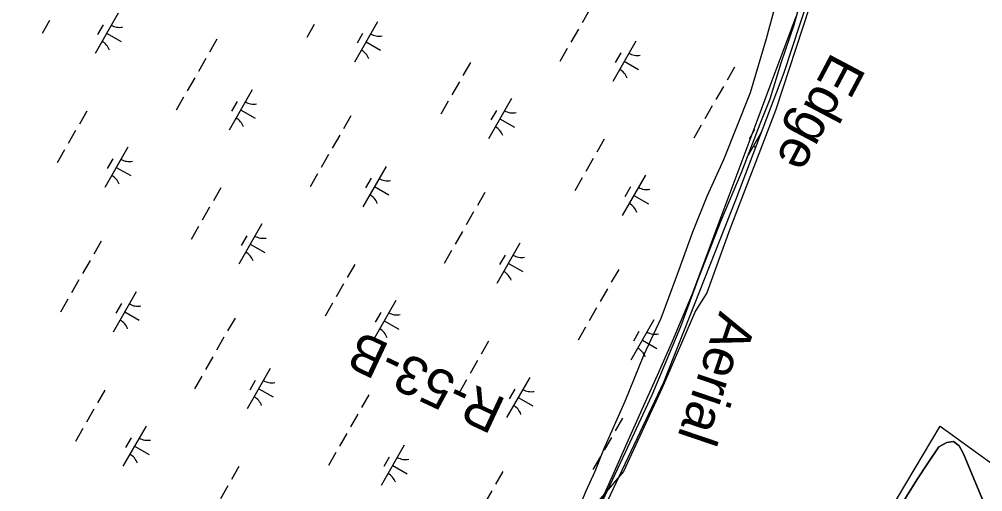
# Model space of a CAD drawing. Extents: x 3930721 to 3950824, y 220441 to 242861.
# Drawn here: x 3939555 to 3940593, y 231818 to 232327 of the extents above; entities that cross this region are included whole.
import ezdxf

# ---------------------------------------------------------------- set-up
doc = ezdxf.new("R2010")
doc.units = 0
for name, color, linetype in [('V-RIVR-EDGE', 7, 'Continuous'), ('V-RIVR-IDEN', 7, 'Continuous'), ('V-RIVR-JETY', 7, 'Continuous'), ('V-RIVR-RANG-IDEN', 7, 'Continuous'), ('V-RRAP-FSHR', 7, 'Continuous'), ('V-TOPO-DPTH', 7, 'Continuous'), ('V-TOPO-MINR', 7, 'Continuous'), ('V-WETL-SWMP', 7, 'Continuous')]:
    doc.layers.add(name, color=color, linetype=linetype)

msp = doc.modelspace()

# ---------------------------------------------------------------- linework, layer by layer
at = {"layer": 'V-RIVR-EDGE'}
msp.add_lwpolyline([(3940577.2, 232885.8), (3940558.8, 232826.5), (3940539.3, 232702.6), (3940479.9, 232552.1), (3940456.4, 232500.9), (3940475.8, 232475.3), (3940468.7, 232441.6), (3940446.1, 232416), (3940426.7, 232394.5), (3940406.2, 232340.2), (3940369.4, 232228.6), (3940320.2, 232100.7), (3940295.7, 232032.1), (3940283.4, 232012.6), (3940247.5, 231929.7), (3940205.6, 231839.6), (3940176.9, 231805.8)], dxfattribs=at)
at = {"layer": 'V-RIVR-JETY'}
for points in [[(3940313.8, 232175.7), (3940342.7, 232248), (3940360, 232306), (3940376.3, 232367.7), (3940382.7, 232392.9), (3940390.4, 232413.5), (3940400.7, 232439.7), (3940410.2, 232460.6)], [(3940461.3, 232442.4), (3940441.4, 232433.4), (3940428.1, 232424.8), (3940420, 232416.9), (3940415.9, 232407.4), (3940406.7, 232384), (3940389.2, 232320.6), (3940375.4, 232279.6), (3940363.4, 232240.7), (3940352.8, 232213.9), (3940332.7, 232161.4), (3940310.5, 232109.7), (3940286.6, 232048.3), (3940267.2, 231995.4), (3940236.4, 231921.8), (3940207.4, 231859.8), (3940177.5, 231795.6)], [(3940156.3, 231796.3), (3940165.7, 231818.8), (3940175.2, 231839.8), (3940185, 231864.4), (3940207.4, 231915.2), (3940227.8, 231965), (3940246.5, 232004.6), (3940263, 232049.2), (3940280.4, 232097.9), (3940296, 232136.2), (3940313.8, 232175.7)]]:
    msp.add_lwpolyline(points, dxfattribs=at)
at = {"layer": 'V-RRAP-FSHR'}
msp.add_lwpolyline([(3940391.6, 232329.6), (3940377.6, 232292.1), (3940363.5, 232254.7), (3940349.5, 232217.2), (3940335.4, 232179.7), (3940321.4, 232142.3), (3940307.3, 232104.8), (3940293.3, 232067.4), (3940279.3, 232029.9), (3940258.2, 231979.5), (3940241.9, 231943), (3940225.6, 231906.4), (3940209.3, 231869.9), (3940193.1, 231833.4), (3940176.7, 231796.9)], dxfattribs=at)
at = {"layer": 'V-TOPO-DPTH'}
msp.add_lwpolyline([(3939138.4, 228899.8), (3939165.6, 228949.6), (3939838.2, 229801.2), (3940275.6, 230709.6), (3940672.4, 231617.7), (3940572, 231858.6), (3940567.3, 231867.1), (3940561.5, 231871.8), (3940554.1, 231870.8), (3940545.6, 231866.1), (3940533.6, 231848.4), (3940521.9, 231830.6), (3940510.6, 231812.5), (3940499.5, 231794.3), (3940486, 231771.5), (3940470.4, 231745.8), (3940454.4, 231720.3), (3940437.9, 231695.2), (3940421, 231670.3), (3940394.3, 231631.9), (3940546.9, 231888.2), (3940838.9, 231677.1)], dxfattribs=at)
at = {"layer": 'V-TOPO-MINR'}
msp.add_lwpolyline([(3940394.3, 231631.9), (3940421, 231670.3), (3940437.9, 231695.2), (3940454.4, 231720.3), (3940470.4, 231745.8), (3940486, 231771.5), (3940499.5, 231794.3), (3940510.6, 231812.5), (3940521.9, 231830.6), (3940533.6, 231848.4), (3940545.6, 231866.1), (3940554.1, 231870.8), (3940561.5, 231871.8), (3940567.3, 231867.1), (3940572, 231858.6), (3940672.4, 231617.7), (3940275.6, 230709.6), (3939838.2, 229801.2), (3939165.6, 228949.6), (3939138.4, 228899.8)], dxfattribs=at)
at = {"layer": 'V-WETL-SWMP'}
for p, q in [((3940379, 232269.5), (3940404.7, 232348.5)), ((3939661.2, 232333.5), (3939636.3, 232290.1)), ((3940169, 232336.9), (3940161.1, 232323.1)), ((3939587.4, 232325.5), (3939579.5, 232311.6)), ((3939645, 232320.8), (3939639.1, 232310.4)), ((3939872.6, 232321.2), (3939864.6, 232307.3)), ((3939940.7, 232324), (3939915.9, 232280.7)), ((3939648.7, 232311.8), (3939664.4, 232302.9)), ((3939924.6, 232311.4), (3939918.6, 232301)), ((3940157.1, 232316.1), (3940149.1, 232302.2)), ((3939767.5, 232305.3), (3939759.6, 232291.4)), ((3939928.3, 232302.4), (3939943.9, 232293.4)), ((3940218.9, 232303.3), (3940194.1, 232259.9)), ((3940145.2, 232295.3), (3940137.2, 232281.4)), ((3940202.8, 232290.6), (3940196.8, 232280.2)), ((3939755.6, 232284.5), (3939747.7, 232270.6)), ((3940040.8, 232280.2), (3940032.8, 232266.3)), ((3940206.5, 232281.6), (3940222.1, 232272.6)), ((3940325.3, 232275.1), (3940317.3, 232261.2)), ((3940326.7, 232132.4), (3940379, 232269.5)), ((3939743.7, 232263.7), (3939735.7, 232249.8)), ((3940028.9, 232259.4), (3940020.9, 232245.5)), ((3939805.5, 232250.8), (3939780.7, 232207.4)), ((3940313.4, 232254.3), (3940305.4, 232240.4)), ((3939731.8, 232242.9), (3939723.8, 232229)), ((3939789.4, 232238.2), (3939783.4, 232227.8)), ((3940016.9, 232238.6), (3940009, 232224.7)), ((3940085, 232241.4), (3940060.2, 232198)), ((3939627.4, 232227.8), (3939619.4, 232213.9)), ((3939793.1, 232229.1), (3939808.7, 232220.2)), ((3940068.9, 232228.7), (3940062.9, 232218.3)), ((3940301.4, 232233.5), (3940293.5, 232219.6)), ((3939911.9, 232222.7), (3939903.9, 232208.8)), ((3940072.6, 232219.7), (3940088.2, 232210.7)), ((3939615.4, 232207), (3939607.5, 232193.1)), ((3940289.5, 232212.6), (3940281.5, 232198.7)), ((3940354.5, 232205.4), (3940338.4, 232177.2)), ((3940347.1, 232208), (3940341.2, 232197.5)), ((3939900, 232201.8), (3939892, 232188)), ((3940185.1, 232197.6), (3940177.2, 232183.7)), ((3940350.8, 232198.9), (3940351.8, 232198.3)), ((3939603.5, 232186.1), (3939595.6, 232172.2)), ((3939671.6, 232188.9), (3939646.8, 232145.6)), ((3939655.5, 232176.3), (3939649.5, 232165.9)), ((3939888, 232181), (3939880.1, 232167.1)), ((3940173.2, 232176.7), (3940165.2, 232162.8)), ((3939659.2, 232167.2), (3939674.8, 232158.3)), ((3939949.9, 232168.2), (3939925, 232124.8)), ((3939876.1, 232160.2), (3939868.1, 232146.3)), ((3939933.7, 232155.5), (3939927.8, 232145.1)), ((3940161.3, 232155.9), (3940153.3, 232142)), ((3940229.4, 232158.7), (3940204.5, 232115.3)), ((3939771.7, 232145.1), (3939763.8, 232131.2)), ((3939937.4, 232146.5), (3939953, 232137.5)), ((3940213.2, 232146.1), (3940207.3, 232135.6)), ((3940056.2, 232140), (3940048.3, 232126.1)), ((3940217, 232137), (3940232.6, 232128.1)), ((3940249.1, 231935.8), (3940326.7, 232132.4)), ((3939759.8, 232124.3), (3939751.8, 232110.4)), ((3940044.3, 232119.2), (3940036.3, 232105.3)), ((3939747.9, 232103.5), (3939739.9, 232089.6)), ((3939816, 232106.3), (3939791.1, 232062.9)), ((3939799.8, 232093.6), (3939793.9, 232083.2)), ((3940032.4, 232098.3), (3940024.4, 232084.5)), ((3939642.8, 232087.6), (3939634.9, 232073.7)), ((3939803.6, 232084.6), (3939819.2, 232075.6)), ((3940094.2, 232085.5), (3940069.3, 232042.1)), ((3940020.4, 232077.5), (3940012.5, 232063.6)), ((3940078.1, 232072.8), (3940072.1, 232062.4)), ((3939630.9, 232066.7), (3939622.9, 232052.9)), ((3939916.1, 232062.5), (3939908.1, 232048.6)), ((3940081.8, 232063.8), (3940097.4, 232054.9)), ((3940298.2, 232060.3), (3940297.7, 232059.3)), ((3940200.6, 232057.3), (3940192.6, 232043.5)), ((3939619, 232045.9), (3939611, 232032)), ((3939904.1, 232041.6), (3939896.2, 232027.7)), ((3939680.8, 232033.1), (3939655.9, 231989.7)), ((3940188.6, 232036.5), (3940180.7, 232022.6)), ((3939607, 232025.1), (3939599.1, 232011.2)), ((3939664.7, 232020.4), (3939658.7, 232010)), ((3939892.2, 232020.8), (3939884.3, 232006.9)), ((3939960.3, 232023.6), (3939935.5, 231980.2)), ((3939668.4, 232011.4), (3939684, 232002.4)), ((3939944.2, 232011), (3939938.2, 232000.5)), ((3940176.7, 232015.7), (3940168.8, 232001.8)), ((3939787.2, 232004.9), (3939779.2, 231991)), ((3939947.9, 232001.9), (3939963.5, 231993)), ((3940238.5, 232002.8), (3940213.7, 231959.4)), ((3940164.8, 231994.9), (3940156.8, 231981)), ((3940222.4, 231990.2), (3940216.4, 231979.8)), ((3939775.2, 231984.1), (3939767.3, 231970.2)), ((3940060.4, 231979.8), (3940052.4, 231965.9)), ((3940226.1, 231981.1), (3940241.7, 231972.2)), ((3939763.3, 231963.2), (3939755.4, 231949.4)), ((3940048.5, 231959), (3940040.5, 231945.1)), ((3939825.1, 231950.4), (3939800.3, 231907)), ((3939751.4, 231942.4), (3939743.4, 231928.5)), ((3939809, 231937.7), (3939803, 231927.3)), ((3940036.5, 231938.1), (3940028.6, 231924.2)), ((3940104.7, 231940.9), (3940079.8, 231897.6)), ((3940166.1, 231760), (3940249.1, 231935.8)), ((3939647, 231927.3), (3939639, 231913.5)), ((3939812.7, 231928.7), (3939828.3, 231919.8)), ((3940088.5, 231928.3), (3940082.6, 231917.9)), ((3939931.5, 231922.2), (3939923.6, 231908.3)), ((3940092.2, 231919.3), (3940107.9, 231910.3)), ((3939635.1, 231906.5), (3939627.1, 231892.6)), ((3939919.6, 231901.4), (3939911.6, 231887.5)), ((3940204.7, 231897.1), (3940196.8, 231883.2)), ((3939623.1, 231885.7), (3939615.2, 231871.8)), ((3939691.3, 231888.5), (3939666.4, 231845.1)), ((3939675.1, 231875.9), (3939669.2, 231865.4)), ((3939907.6, 231880.6), (3939899.7, 231866.7)), ((3940192.8, 231876.3), (3940184.9, 231862.4)), ((3939678.8, 231866.8), (3939694.5, 231857.9)), ((3939969.5, 231867.7), (3939944.6, 231824.3)), ((3939895.7, 231859.8), (3939887.8, 231845.9)), ((3939953.3, 231855.1), (3939947.4, 231844.7)), ((3940180.9, 231855.5), (3940172.9, 231841.6)), ((3939791.3, 231844.7), (3939783.4, 231830.8)), ((3939957.1, 231846), (3939972.7, 231837.1)), ((3940075.8, 231839.6), (3940067.9, 231825.7)), ((3939779.4, 231823.9), (3939771.5, 231810)), ((3940063.9, 231818.7), (3940056, 231804.9))]:
    msp.add_line(p, q, dxfattribs=at)
for centre, start, end in [((3939662.7, 232335.7), 239.4279, 280.9715), ((3939942.2, 232326.2), 239.4279, 280.9715), ((3939635.2, 232287.7), 19.4279, 60.9715), ((3939914.8, 232278.3), 19.4279, 60.9715), ((3940220.4, 232305.4), 239.4279, 280.9715), ((3940193, 232257.5), 19.4279, 60.9715), ((3939807, 232253), 239.4279, 280.9715), ((3940086.6, 232243.5), 239.4279, 280.9715), ((3939779.6, 232205.1), 19.4279, 60.9715), ((3940059.1, 232195.6), 19.4279, 60.9715), ((3940337.3, 232174.8), 51.9723, 60.9715), ((3939673.2, 232191.1), 239.4279, 280.9715), ((3939645.7, 232143.2), 19.4279, 60.9715), ((3939951.4, 232170.3), 239.4279, 280.9715), ((3940230.9, 232160.9), 239.4279, 280.9715), ((3939923.9, 232122.4), 19.4279, 60.9715), ((3940203.4, 232112.9), 19.4279, 60.9715), ((3939817.5, 232108.4), 239.4279, 280.9715), ((3939790, 232060.5), 19.4279, 60.9715), ((3940095.7, 232087.7), 239.4279, 280.9715), ((3940068.2, 232039.7), 19.4279, 60.9715), ((3939682.3, 232035.2), 239.4279, 280.9715), ((3939961.8, 232025.8), 239.4279, 280.9715), ((3939654.8, 231987.3), 19.4279, 60.9715), ((3939934.4, 231977.8), 19.4279, 60.9715), ((3940240, 232005), 239.4279, 280.9715), ((3940212.6, 231957.1), 19.4279, 60.9715), ((3939826.6, 231952.6), 239.4279, 280.9715), ((3940106.2, 231943.1), 239.4279, 280.9715), ((3939799.2, 231904.6), 19.4279, 60.9715), ((3940078.7, 231895.2), 19.4279, 60.9715), ((3939692.8, 231890.7), 239.4279, 280.9715), ((3939665.3, 231842.7), 19.4279, 60.9715), ((3939971, 231869.9), 239.4279, 280.9715), ((3939943.5, 231822), 19.4279, 60.9715)]:
    msp.add_arc(centre, 17.6, start, end, dxfattribs=at)

# ---------------------------------------------------------------- texts
at = {"layer": 'V-RIVR-IDEN'}
for s, rotation, p in [('Edge', 242.1102, (3940430.6, 232292.6)), ('Aerial', 251.2826, (3940309.7, 232013.2))]:
    msp.add_text(s, height=42, rotation=rotation, dxfattribs=at).set_placement(p)
at = {"layer": 'V-RIVR-RANG-IDEN'}
msp.add_text('R-53-B', height=41.5, rotation=154.8318, dxfattribs=at).set_placement((3940080.9, 231916.7))

doc.saveas('drawing.dxf')
